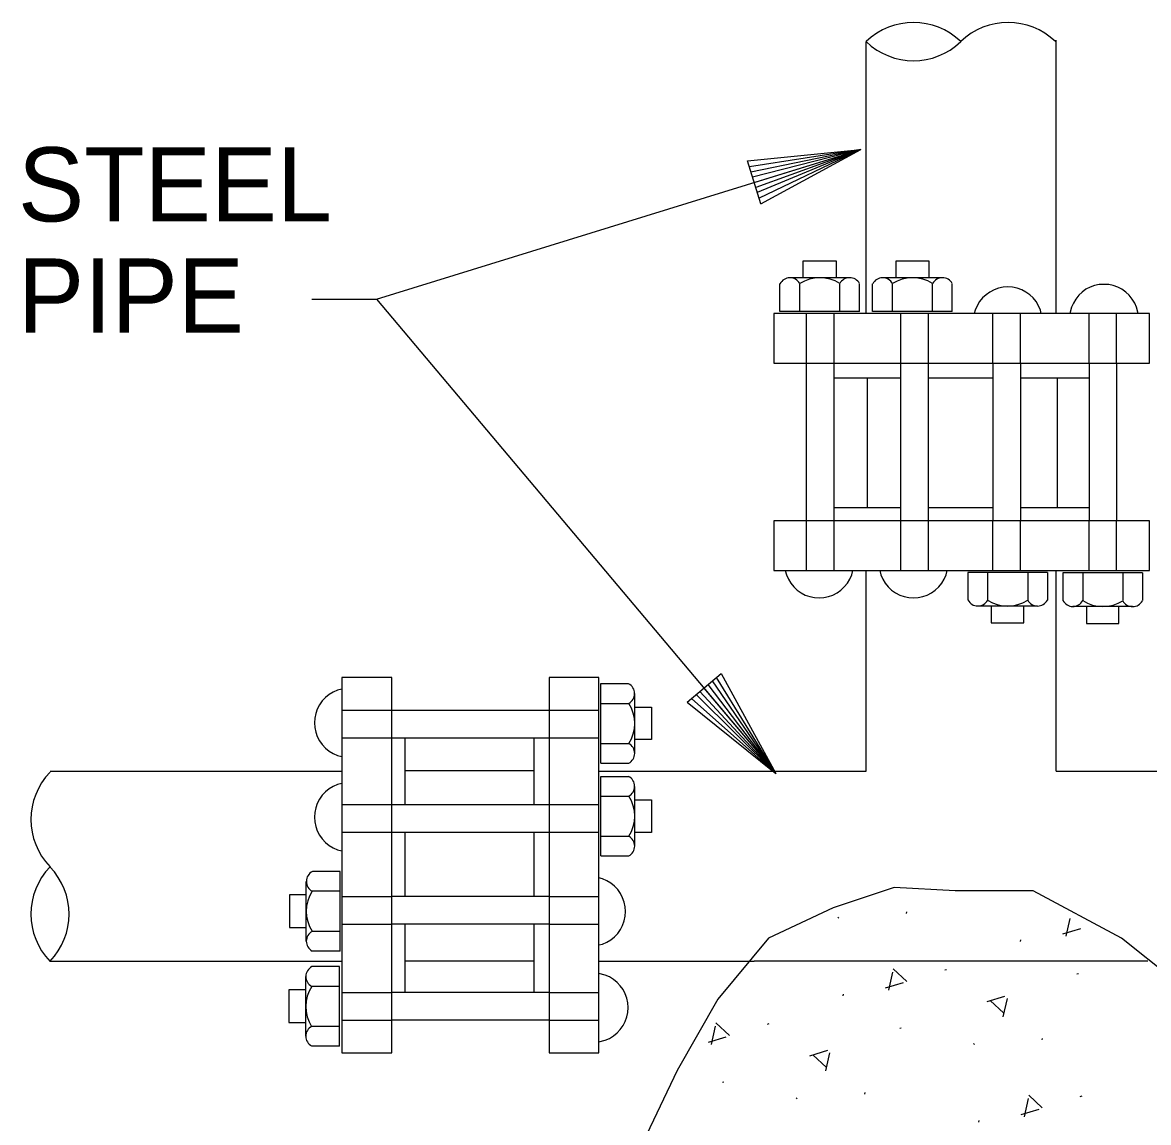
# Model space of a CAD drawing. Extents: x 10040.55 to 10045.84, y 10033.26 to 10035.76.
# Drawn here: x 10041.8134 to 10041.9653, y 10034.4745 to 10034.6229 of the extents above; entities that cross this region are included whole.
import ezdxf

# ---------------------------------------------------------------- set-up
doc = ezdxf.new("R2010")
doc.units = 0
doc.layers.add('Level 2', color=7, linetype='Continuous')

msp = doc.modelspace()

# ---------------------------------------------------------------- linework, layer by layer
at = {"layer": 'Level 2'}
for p, q in [((10041.92721, 10034.58365), (10041.92721, 10034.62031)), ((10041.95282, 10034.58365), (10041.95282, 10034.62053)), ((10041.91123, 10034.60421), (10041.9265, 10034.60576)), ((10041.9265, 10034.60576), (10041.91147, 10034.60342)), ((10041.9265, 10034.60576), (10041.91167, 10034.60272)), ((10041.9265, 10034.60576), (10041.9119, 10034.60201)), ((10041.91211, 10034.60129), (10041.9265, 10034.60576)), ((10041.9265, 10034.60576), (10041.91233, 10034.60063)), ((10041.9265, 10034.60576), (10041.91251, 10034.59998)), ((10041.9265, 10034.60576), (10041.91278, 10034.59918)), ((10041.913, 10034.59845), (10041.9265, 10034.60576)), ((10041.913, 10034.59845), (10041.91123, 10034.60421)), ((10041.92497, 10034.58847), (10041.91693, 10034.58847)), ((10041.93748, 10034.58847), (10041.92944, 10034.58847)), ((10041.91558, 10034.58392), (10041.91558, 10034.58763)), ((10041.91826, 10034.58392), (10041.91826, 10034.58766)), ((10041.92366, 10034.58392), (10041.92366, 10034.58766)), ((10041.92632, 10034.58392), (10041.92632, 10034.58766)), ((10041.92809, 10034.58392), (10041.92809, 10034.58763)), ((10041.93077, 10034.58392), (10041.93077, 10034.58766)), ((10041.93617, 10034.58392), (10041.93617, 10034.58766)), ((10041.93883, 10034.58392), (10041.93883, 10034.58766)), ((10041.92632, 10034.58392), (10041.91558, 10034.58392)), ((10041.91917, 10034.57692), (10041.91917, 10034.58365)), ((10041.92289, 10034.57692), (10041.92289, 10034.58365)), ((10041.93883, 10034.58392), (10041.92809, 10034.58392)), ((10041.9319, 10034.57692), (10041.9319, 10034.58365)), ((10041.93561, 10034.57692), (10041.93561, 10034.58365)), ((10041.9443, 10034.57692), (10041.9443, 10034.58365)), ((10041.94802, 10034.57692), (10041.94802, 10034.58365)), ((10041.95727, 10034.57692), (10041.95727, 10034.58365)), ((10041.96099, 10034.57692), (10041.96099, 10034.58365)), ((10041.91917, 10034.55569), (10041.91917, 10034.57692)), ((10041.92289, 10034.55569), (10041.92289, 10034.57692)), ((10041.9319, 10034.55569), (10041.9319, 10034.57692)), ((10041.93561, 10034.55569), (10041.93561, 10034.57692)), ((10041.9443, 10034.57692), (10041.9443, 10034.55569)), ((10041.94802, 10034.57692), (10041.94802, 10034.55569)), ((10041.95727, 10034.57692), (10041.95727, 10034.55569)), ((10041.96099, 10034.57692), (10041.96099, 10034.55569)), ((10041.93186, 10034.5749), (10041.92289, 10034.5749)), ((10041.92736, 10034.57489), (10041.92736, 10034.55754)), ((10041.94431, 10034.5749), (10041.9356, 10034.5749)), ((10041.95727, 10034.5749), (10041.94805, 10034.5749)), ((10041.953, 10034.55754), (10041.953, 10034.57489)), ((10041.92289, 10034.55748), (10041.93186, 10034.55748)), ((10041.9356, 10034.55748), (10041.94431, 10034.55748)), ((10041.94805, 10034.55748), (10041.95727, 10034.55748)), ((10041.91917, 10034.54898), (10041.91917, 10034.55571)), ((10041.92289, 10034.54898), (10041.92289, 10034.55571)), ((10041.9319, 10034.54898), (10041.9319, 10034.55571)), ((10041.93561, 10034.54898), (10041.93561, 10034.55571)), ((10041.9443, 10034.54898), (10041.9443, 10034.55571)), ((10041.94802, 10034.54898), (10041.94802, 10034.55571)), ((10041.95727, 10034.54898), (10041.95727, 10034.55571)), ((10041.96099, 10034.54898), (10041.96099, 10034.55571)), ((10041.92721, 10034.52191), (10041.92721, 10034.54896)), ((10041.95167, 10034.54872), (10041.94093, 10034.54872)), ((10041.94093, 10034.54872), (10041.94093, 10034.54501)), ((10041.9436, 10034.54872), (10041.9436, 10034.54498)), ((10041.949, 10034.54872), (10041.949, 10034.54498)), ((10041.95167, 10034.54872), (10041.95167, 10034.54498)), ((10041.95282, 10034.52191), (10041.95282, 10034.54896)), ((10041.96449, 10034.54865), (10041.95375, 10034.54865)), ((10041.95375, 10034.54865), (10041.95375, 10034.54494)), ((10041.95643, 10034.54865), (10041.95643, 10034.54491)), ((10041.96182, 10034.54865), (10041.96182, 10034.54491)), ((10041.96449, 10034.54865), (10041.96449, 10034.54491)), ((10041.95031, 10034.54417), (10041.94227, 10034.54417)), ((10041.96314, 10034.54409), (10041.95509, 10034.54409)), ((10041.90306, 10034.53119), (10041.90768, 10034.53506)), ((10041.90768, 10034.53506), (10041.91505, 10034.5216)), ((10041.89145, 10034.52297), (10041.89145, 10034.53371)), ((10041.89145, 10034.53371), (10041.89516, 10034.53371)), ((10041.91505, 10034.5216), (10041.90592, 10034.53359)), ((10041.91505, 10034.5216), (10041.90648, 10034.53408)), ((10041.91505, 10034.5216), (10041.90704, 10034.53454)), ((10041.896, 10034.52432), (10041.896, 10034.53236)), ((10041.91505, 10034.5216), (10041.90427, 10034.53224)), ((10041.91505, 10034.5216), (10041.9048, 10034.53266)), ((10041.90533, 10034.53311), (10041.91505, 10034.5216)), ((10041.89145, 10034.53103), (10041.89519, 10034.53103)), ((10041.90306, 10034.53119), (10041.91505, 10034.5216)), ((10041.91505, 10034.5216), (10041.90365, 10034.53168)), ((10041.85651, 10034.53013), (10041.86324, 10034.53013)), ((10041.86322, 10034.53013), (10041.88445, 10034.53013)), ((10041.88445, 10034.53013), (10041.89118, 10034.53013)), ((10041.85651, 10034.52641), (10041.86324, 10034.52641)), ((10041.86322, 10034.52641), (10041.88445, 10034.52641)), ((10041.86501, 10034.52641), (10041.86501, 10034.51743)), ((10041.88243, 10034.51743), (10041.88243, 10034.52641)), ((10041.88445, 10034.52641), (10041.89118, 10034.52641)), ((10041.89145, 10034.52564), (10041.89519, 10034.52564)), ((10041.89145, 10034.52297), (10041.89519, 10034.52297)), ((10041.81714, 10034.52191), (10041.85649, 10034.52191)), ((10041.88242, 10034.52193), (10041.86507, 10034.52193)), ((10041.89118, 10034.52191), (10041.92721, 10034.52191)), ((10041.89145, 10034.51046), (10041.89145, 10034.5212)), ((10041.89145, 10034.5212), (10041.89516, 10034.5212)), ((10041.95282, 10034.52191), (10041.98391, 10034.52191)), ((10041.896, 10034.51181), (10041.896, 10034.51985)), ((10041.89145, 10034.51852), (10041.89519, 10034.51852)), ((10041.85651, 10034.5174), (10041.86324, 10034.5174)), ((10041.86322, 10034.5174), (10041.88445, 10034.5174)), ((10041.88445, 10034.5174), (10041.89118, 10034.5174)), ((10041.85651, 10034.51368), (10041.86324, 10034.51368)), ((10041.86322, 10034.51368), (10041.88445, 10034.51368)), ((10041.86501, 10034.51369), (10041.86501, 10034.50498)), ((10041.88243, 10034.50498), (10041.88243, 10034.51369)), ((10041.88445, 10034.51368), (10041.89118, 10034.51368)), ((10041.89145, 10034.51313), (10041.89519, 10034.51313)), ((10041.89145, 10034.51046), (10041.89519, 10034.51046)), ((10041.85625, 10034.50836), (10041.85254, 10034.50836)), ((10041.85625, 10034.49763), (10041.85625, 10034.50836)), ((10041.8517, 10034.49898), (10041.8517, 10034.50702)), ((10041.85625, 10034.50569), (10041.85251, 10034.50569)), ((10041.85651, 10034.50499), (10041.86324, 10034.50499)), ((10041.88445, 10034.50499), (10041.86322, 10034.50499)), ((10041.88445, 10034.50499), (10041.89118, 10034.50499)), ((10041.92354, 10034.50207), (10041.9234, 10034.50221)), ((10041.93265, 10034.5029), (10041.9326, 10034.5027)), ((10041.95469, 10034.50202), (10041.95414, 10034.49965)), ((10041.85625, 10034.50029), (10041.85251, 10034.50029)), ((10041.85651, 10034.50127), (10041.86324, 10034.50127)), ((10041.88445, 10034.50127), (10041.86322, 10034.50127)), ((10041.86501, 10034.50124), (10041.86501, 10034.49202)), ((10041.88243, 10034.49202), (10041.88243, 10034.50124)), ((10041.88445, 10034.50127), (10041.89118, 10034.50127)), ((10041.95376, 10034.49996), (10041.95615, 10034.50069)), ((10041.94804, 10034.49892), (10041.94808, 10034.49913)), ((10041.85625, 10034.49763), (10041.85251, 10034.49763)), ((10041.81714, 10034.49628), (10041.85649, 10034.49628)), ((10041.85618, 10034.49554), (10041.85247, 10034.49554)), ((10041.85618, 10034.4848), (10041.85618, 10034.49554)), ((10041.86507, 10034.49629), (10041.88242, 10034.49629)), ((10041.89118, 10034.49628), (10041.9121, 10034.49628)), ((10041.96519, 10034.49628), (10041.9121, 10034.49628)), ((10041.85163, 10034.48616), (10041.85163, 10034.4942)), ((10041.93077, 10034.49478), (10041.93021, 10034.49234)), ((10041.93269, 10034.49354), (10041.93086, 10034.49525)), ((10041.93782, 10034.49508), (10041.93805, 10034.49516)), ((10041.95584, 10034.49455), (10041.95565, 10034.4945)), ((10041.85618, 10034.49286), (10041.85244, 10034.49286)), ((10041.92984, 10034.49265), (10041.93224, 10034.49339)), ((10041.85651, 10034.49202), (10041.86324, 10034.49202)), ((10041.88445, 10034.49202), (10041.86322, 10034.49202)), ((10041.88445, 10034.49202), (10041.89118, 10034.49202)), ((10041.92411, 10034.49161), (10041.92417, 10034.49181)), ((10041.94589, 10034.49151), (10041.94349, 10034.49078)), ((10041.94394, 10034.49095), (10041.94577, 10034.48925)), ((10041.9457, 10034.48877), (10041.94626, 10034.49121)), ((10041.85651, 10034.4883), (10041.86324, 10034.4883)), ((10041.88445, 10034.4883), (10041.86322, 10034.4883)), ((10041.88445, 10034.4883), (10041.89118, 10034.4883)), ((10041.90877, 10034.48622), (10041.90694, 10034.48793)), ((10041.91391, 10034.48778), (10041.91415, 10034.48785)), ((10041.85618, 10034.48747), (10041.85244, 10034.48747)), ((10041.90685, 10034.48748), (10041.90629, 10034.48504)), ((10041.93194, 10034.48725), (10041.93174, 10034.48719)), ((10041.85618, 10034.4848), (10041.85244, 10034.4848)), ((10041.90594, 10034.48534), (10041.90833, 10034.48607)), ((10041.94183, 10034.48502), (10041.94168, 10034.48517)), ((10041.95095, 10034.48584), (10041.95091, 10034.48565)), ((10041.92198, 10034.4842), (10041.91958, 10034.48347)), ((10041.92002, 10034.48363), (10041.92185, 10034.48193)), ((10041.92177, 10034.48147), (10041.92233, 10034.4839)), ((10041.90803, 10034.47994), (10041.90783, 10034.47988)), ((10041.91792, 10034.4777), (10041.91776, 10034.47784)), ((10041.92703, 10034.47854), (10041.92698, 10034.47833)), ((10041.94907, 10034.47773), (10041.94851, 10034.47529)), ((10041.95097, 10034.4765), (10041.94915, 10034.4782)), ((10041.9561, 10034.47802), (10041.95634, 10034.47809)), ((10041.94814, 10034.47558), (10041.95053, 10034.47631)), ((10041.94242, 10034.47456), (10041.94246, 10034.47476))]:
    msp.add_line(p, q, dxfattribs=at)
for points in [[(10041.85244, 10034.58556), (10041.86119, 10034.58556), (10041.9265, 10034.60576)], [(10041.91874, 10034.58849), (10041.91874, 10034.59075), (10041.92315, 10034.59075), (10041.92315, 10034.58849)], [(10041.93125, 10034.58849), (10041.93125, 10034.59075), (10041.93566, 10034.59075), (10041.93566, 10034.58849)], [(10041.95084, 10034.58365), (10041.95072, 10034.5841), (10041.95047, 10034.58469), (10041.95014, 10034.58524), (10041.94973, 10034.58573), (10041.94927, 10034.58617), (10041.94875, 10034.58653), (10041.94819, 10034.58682), (10041.94758, 10034.58704), (10041.94696, 10034.58717), (10041.94632, 10034.58722), (10041.94569, 10034.58717), (10041.94506, 10034.58704), (10041.94446, 10034.58682), (10041.9439, 10034.58653), (10041.94338, 10034.58617), (10041.94292, 10034.58573), (10041.94251, 10034.58524), (10041.94219, 10034.58469), (10041.94193, 10034.5841), (10041.9418, 10034.58365)], [(10041.96391, 10034.58365), (10041.96369, 10034.58447), (10041.96344, 10034.58505), (10041.9631, 10034.58559), (10041.9627, 10034.58609), (10041.96224, 10034.58652), (10041.96172, 10034.5869), (10041.96116, 10034.58719), (10041.96055, 10034.58741), (10041.95993, 10034.58753), (10041.95929, 10034.58757), (10041.95866, 10034.58753), (10041.95803, 10034.58741), (10041.95744, 10034.58719), (10041.95686, 10034.5869), (10041.95634, 10034.58652), (10041.95589, 10034.58609), (10041.95548, 10034.58559), (10041.95516, 10034.58505), (10041.9549, 10034.58447), (10041.95468, 10034.58365)], [(10041.86119, 10034.58556), (10041.91505, 10034.5216)], [(10041.91631, 10034.54896), (10041.91647, 10034.54838), (10041.91673, 10034.54779), (10041.91705, 10034.54725), (10041.91746, 10034.54675), (10041.91792, 10034.54631), (10041.91844, 10034.54595), (10041.91901, 10034.54566), (10041.9196, 10034.54544), (10041.92023, 10034.54531), (10041.92086, 10034.54527), (10041.9215, 10034.54531), (10041.92213, 10034.54544), (10041.92273, 10034.54566), (10041.92329, 10034.54595), (10041.92381, 10034.54631), (10041.92427, 10034.54675), (10041.92468, 10034.54725), (10041.92501, 10034.54779), (10041.92526, 10034.54838), (10041.92542, 10034.54896)], [(10041.92904, 10034.54896), (10041.9292, 10034.54838), (10041.92946, 10034.54779), (10041.92978, 10034.54725), (10041.93019, 10034.54675), (10041.93065, 10034.54631), (10041.93117, 10034.54595), (10041.93174, 10034.54566), (10041.93233, 10034.54544), (10041.93296, 10034.54531), (10041.93359, 10034.54527), (10041.93423, 10034.54531), (10041.93485, 10034.54544), (10041.93546, 10034.54566), (10041.93602, 10034.54595), (10041.93654, 10034.54631), (10041.937, 10034.54675), (10041.93741, 10034.54725), (10041.93774, 10034.54779), (10041.93799, 10034.54838), (10041.93815, 10034.54896)], [(10041.94408, 10034.54415), (10041.94408, 10034.54189), (10041.94849, 10034.54189), (10041.94849, 10034.54415)], [(10041.95691, 10034.54407), (10041.95691, 10034.54181), (10041.96131, 10034.54181), (10041.96131, 10034.54407)], [(10041.85649, 10034.53298), (10041.85591, 10034.53282), (10041.85532, 10034.53256), (10041.85478, 10034.53224), (10041.85428, 10034.53183), (10041.85384, 10034.53138), (10041.85348, 10034.53085), (10041.85319, 10034.53028), (10041.85297, 10034.52969), (10041.85284, 10034.52906), (10041.8528, 10034.52843), (10041.85284, 10034.52779), (10041.85297, 10034.52717), (10041.85319, 10034.52656), (10041.85348, 10034.526), (10041.85384, 10034.52548), (10041.85428, 10034.52502), (10041.85478, 10034.52461), (10041.85532, 10034.52428), (10041.85591, 10034.52403), (10041.85649, 10034.52388)], [(10041.89602, 10034.53055), (10041.89828, 10034.53055), (10041.89828, 10034.52615), (10041.89602, 10034.52615)], [(10041.85649, 10034.52025), (10041.85591, 10034.52009), (10041.85532, 10034.51983), (10041.85478, 10034.51951), (10041.85428, 10034.5191), (10041.85384, 10034.51865), (10041.85348, 10034.51813), (10041.85319, 10034.51755), (10041.85297, 10034.51696), (10041.85284, 10034.51633), (10041.8528, 10034.5157), (10041.85284, 10034.51506), (10041.85297, 10034.51444), (10041.85319, 10034.51383), (10041.85348, 10034.51327), (10041.85384, 10034.51275), (10041.85428, 10034.51229), (10041.85478, 10034.51189), (10041.85532, 10034.51155), (10041.85591, 10034.5113), (10041.85649, 10034.51115)], [(10041.89602, 10034.51804), (10041.89828, 10034.51804), (10041.89828, 10034.51364), (10041.89602, 10034.51364)], [(10041.89118, 10034.49845), (10041.89164, 10034.49857), (10041.89222, 10034.49882), (10041.89277, 10034.49916), (10041.89326, 10034.49956), (10041.8937, 10034.50002), (10041.89406, 10034.50054), (10041.89435, 10034.5011), (10041.89457, 10034.50171), (10041.8947, 10034.50233), (10041.89475, 10034.50297), (10041.8947, 10034.5036), (10041.89457, 10034.50423), (10041.89435, 10034.50483), (10041.89406, 10034.5054), (10041.8937, 10034.50592), (10041.89326, 10034.50638), (10041.89277, 10034.50678), (10041.89222, 10034.5071), (10041.89164, 10034.50736), (10041.89118, 10034.50749)], [(10041.98406, 10034.45819), (10041.97995, 10034.47145), (10041.97674, 10034.47923), (10041.97217, 10034.48609), (10041.96851, 10034.49388), (10041.96165, 10034.49936), (10041.94975, 10034.50577), (10041.93923, 10034.50577), (10041.93099, 10034.50622), (10041.92275, 10034.50348), (10041.91406, 10034.49936), (10041.9072, 10034.49113), (10041.90171, 10034.48152), (10041.89714, 10034.47191), (10041.89422, 10034.45785)], [(10041.85168, 10034.50521), (10041.84942, 10034.50521), (10041.84942, 10034.5008), (10041.85168, 10034.5008)], [(10041.89118, 10034.48539), (10041.892, 10034.4856), (10041.89258, 10034.48585), (10041.89313, 10034.48619), (10041.89363, 10034.48659), (10041.89405, 10034.48705), (10041.89443, 10034.48757), (10041.89472, 10034.48814), (10041.89494, 10034.48874), (10041.89506, 10034.48936), (10041.8951, 10034.49), (10041.89506, 10034.49064), (10041.89494, 10034.49126), (10041.89472, 10034.49185), (10041.89443, 10034.49243), (10041.89405, 10034.49295), (10041.89363, 10034.49341), (10041.89313, 10034.49381), (10041.89258, 10034.49414), (10041.892, 10034.4944), (10041.89118, 10034.49461)], [(10041.8516, 10034.49239), (10041.84934, 10034.49239), (10041.84934, 10034.48798), (10041.8516, 10034.48798)]]:
    msp.add_lwpolyline(points, dxfattribs=at)
for points in [[(10041.91474, 10034.57692), (10041.96541, 10034.57692), (10041.96541, 10034.58365), (10041.91474, 10034.58365)], [(10041.91474, 10034.54896), (10041.96541, 10034.54896), (10041.96541, 10034.55569), (10041.91474, 10034.55569)], [(10041.85649, 10034.53455), (10041.85649, 10034.48389), (10041.86322, 10034.48389), (10041.86322, 10034.53455)], [(10041.88445, 10034.53455), (10041.88445, 10034.48389), (10041.89118, 10034.48389), (10041.89118, 10034.53455)]]:
    msp.add_lwpolyline(points, close=True, dxfattribs=at)
for centre, radius, start, end in [((10041.93359, 10034.61371), 0.00918, 45.9775, 134.0212), ((10041.94635, 10034.61371), 0.00918, 45.9788, 134.0225), ((10041.93359, 10034.62691), 0.00918, 225.9788, 314.0225), ((10041.91693, 10034.58696), 0.0015, 28.1609, 153.2173), ((10041.92096, 10034.58351), 0.00496, 57.057, 122.9938), ((10041.92499, 10034.58697), 0.0015, 27.9658, 152.1123), ((10041.92944, 10034.58696), 0.0015, 28.1609, 153.2173), ((10041.93347, 10034.58351), 0.00496, 57.057, 122.9938), ((10041.9375, 10034.58697), 0.0015, 27.9658, 152.1123), ((10041.94228, 10034.54568), 0.0015, 206.7827, 331.8391), ((10041.9463, 10034.54913), 0.00496, 237.0062, 302.943), ((10041.95033, 10034.54567), 0.0015, 207.8877, 332.0342), ((10041.9551, 10034.54561), 0.0015, 206.7827, 331.8391), ((10041.95913, 10034.54906), 0.00496, 237.0062, 302.943), ((10041.96315, 10034.54559), 0.0015, 207.8877, 332.0342), ((10041.89449, 10034.53236), 0.0015, 298.1609, 63.2173), ((10041.89104, 10034.52833), 0.00496, 327.057, 32.9938), ((10041.8945, 10034.5243), 0.0015, 297.9658, 62.1123), ((10041.82374, 10034.51538), 0.00918, 135.9788, 224.0225), ((10041.89449, 10034.51985), 0.0015, 298.1609, 63.2173), ((10041.89104, 10034.51582), 0.00496, 327.057, 32.9938), ((10041.8945, 10034.51179), 0.0015, 297.9658, 62.1123), ((10041.82374, 10034.50262), 0.00918, 135.9775, 224.0212), ((10041.81053, 10034.50262), 0.00918, 315.9788, 44.0225), ((10041.85321, 10034.50702), 0.0015, 116.7827, 241.8391), ((10041.85666, 10034.50299), 0.00496, 147.0062, 212.943), ((10041.8532, 10034.49896), 0.0015, 117.8877, 242.0342), ((10041.85314, 10034.49419), 0.0015, 116.7827, 241.8391), ((10041.85659, 10034.49016), 0.00496, 147.0062, 212.943), ((10041.85313, 10034.48614), 0.0015, 117.8877, 242.0342)]:
    msp.add_arc(centre, radius, start, end, dxfattribs=at)

# ---------------------------------------------------------------- texts
for s, p in [('STEEL', (10041.81282, 10034.59606)), ('PIPE', (10041.81282, 10034.58106))]:
    msp.add_text(s, height=0.01, dxfattribs=at).set_placement(p)

doc.saveas('drawing.dxf')
